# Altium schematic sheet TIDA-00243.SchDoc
size 431 x 279 mm; Date: Not shown in title block; ApprovedBy: Not shown in title block; CheckedBy: Not shown in title block; Author: Not shown in title block; CompanyName: Not shown in title block; DrawnBy: Gordon Varney; Engineer: Not shown in title block; Organization: Not shown in title block; Address1: Not shown in title block; Address2: Not shown in title block; Address3: Not shown in title block; Address4: Not shown in title block; DocumentNumber: 1; Revision: Use project parameter SCH_Rev; SheetNumber: 1; SheetTotal: 1; PageSetup: Record=PageOptions|CenterHorizontal=True|CenterVertical=True|PrintScale=0.64|XCorrection=1.00|YCorrection=1.00|PrintKind=0|BorderSize=5000000|LeftOffset=0|BottomOffset=0|Orientation=2|PaperLength=1000|PaperWidth=1000|Scale=100|PaperSource=15|PrintQuality=600|MediaType=1|DitherType=10|PaperKind=Letter|PrintScaleMode=1
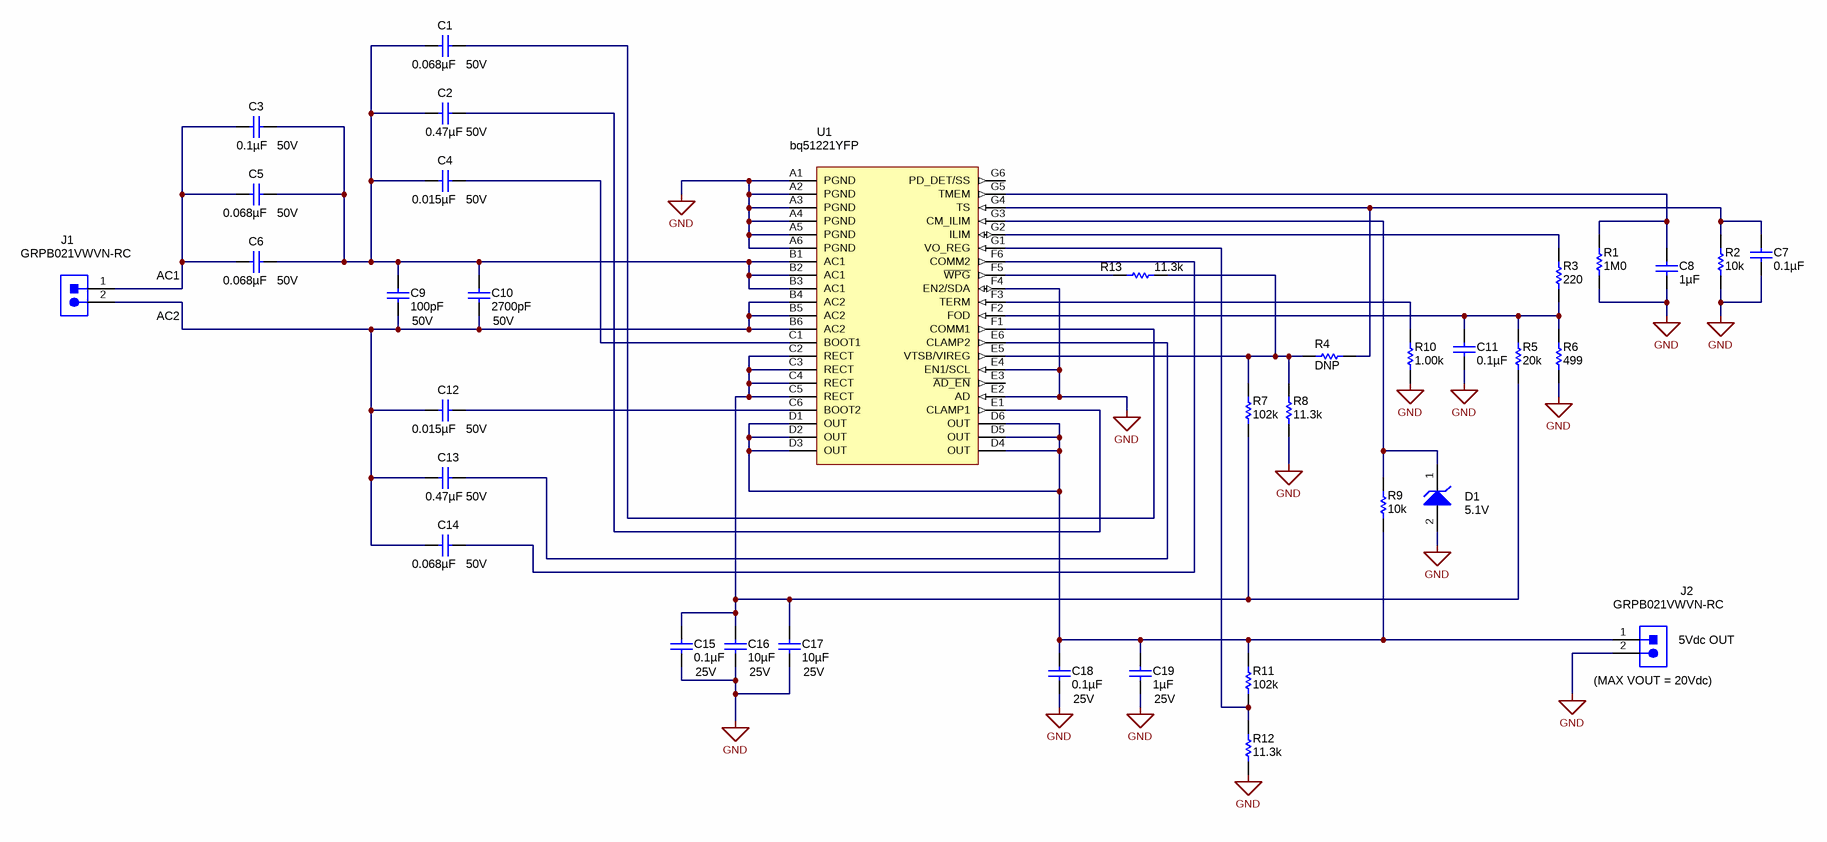
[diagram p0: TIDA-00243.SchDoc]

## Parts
C1  ValueDisplayed: 0.068µF  Value2: 50V  [0402]  (hidden comment: C1005X7R1H683K)
C2  ValueDisplayed: 0.47µF  Value2: 50V  [0402]  (hidden comment: UMK105ABJ474KV-F)
C3  ValueDisplayed: 0.1µF  Value2: 50V  [0402]  (hidden comment: C1005X7R1H104K)
C4  ValueDisplayed: 0.015µF  Value2: 50V  [0402]  (hidden comment: GRM155R71H153KA12D)
C5  ValueDisplayed: 0.068µF  Value2: 50V  [0402]  (hidden comment: C1005X7R1H683K)
C6  ValueDisplayed: 0.068µF  Value2: 50V  [0402]  (hidden comment: C1005X7R1H683K)
C7  ValueDisplayed: 0.1µF  [0201]  (hidden comment: C0603X5R1E104K030BB)
C8  ValueDisplayed: 1µF  [0201]  (hidden comment: CL03A105MP3NSNC)
C9  ValueDisplayed: 100pF  Value2: 50V  [0402]  (hidden comment: GRM1555C1H101JA01D)
C10  ValueDisplayed: 2700pF  Value2: 50V  [0402]  (hidden comment: GRM155R71H272KA01J)
C11  ValueDisplayed: 0.1µF  [0201]  (hidden comment: C0603X5R1E104K030BB)
C12  ValueDisplayed: 0.015µF  Value2: 50V  [0402]  (hidden comment: GRM155R71H153KA12D)
C13  ValueDisplayed: 0.47µF  Value2: 50V  [0402]  (hidden comment: UMK105ABJ474KV-F)
C14  ValueDisplayed: 0.068µF  Value2: 50V  [0402]  (hidden comment: C1005X7R1H683K)
C15  ValueDisplayed: 0.1µF  Value2: 25V  [0201]  (hidden comment: C0603X5R1E104K030BB)
C16  ValueDisplayed: 10µF  Value2: 25V  [0603]  (hidden comment: GRM188R61E106MA73D)
C17  ValueDisplayed: 10µF  Value2: 25V  [0603]  (hidden comment: GRM188R61E106MA73D)
C18  ValueDisplayed: 0.1µF  Value2: 25V  [0201]  (hidden comment: C0603X5R1E104K030BB)
C19  ValueDisplayed: 1µF  Value2: 25V  [0402]  (hidden comment: CGB2A1X5R1E105K033BC)
D1  value 5.1V  [SOD-523]  (hidden comment: BZT52C5V1T-7)
J1  GRPB021VWVN-RC  [Sullins_GRPB021VWVN-RC]
J2  GRPB021VWVN-RC  [Sullins_GRPB021VWVN-RC]
R1  value 1M0  [0201M]  (hidden comment: ERJ-1GEF1004C)
R2  value 10k  [0201M]  (hidden comment: ERJ-1GEF1002C)
R3  value 220  [0201M]  (hidden comment: ERJ-1GEF2200C)
R4  value DNP  [0201M]  (hidden comment: ERJ-1GEF2002C)
R5  value 20k  [0201M]  (hidden comment: ERJ-1GEF2002C)
R6  value 499  [0201M]  (hidden comment: ERJ-1GEF4990C)
R7  value 102k  [0201M]  (hidden comment: ERJ-1GEF1023C)
R8  value 11.3k  [0201M]  (hidden comment: ERJ-1GEF1132C)
R9  value 10k  [0201M]  (hidden comment: ERJ-1GEF1002C)
R10  value 1.00k  [0201M]  (hidden comment: ERJ-1GEF1001C)
R11  value 102k  [0201M]  (hidden comment: ERJ-1GEF1023C)
R12  value 11.3k  [0201M]  (hidden comment: ERJ-1GEF1132C)
R13  value 11.3k  [0201M]  (hidden comment: ERJ-1GEF1132C)
U1  bq5102x  [YFP0042AWCG]  (value not drawn)

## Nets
GND: C7.2 C8.2 C11.2 C15.2 C16.2 C17.2 C18.2 C19.2 D1.2(A) J2.2 R1.1 R2.1 R6.1 R8.1 R10.1 R12.1 U1.A1(PGND) U1.A2(PGND) U1.A3(PGND) U1.A4(PGND) U1.A5(PGND) U1.A6(PGND) U1.E2(AD) U1.E4(EN1/SCL) U1.F4(EN2/SDA)
NetC1_1: C1.1 U1.F1(COMM1)
NetC1_2: C1.2 C2.2 C3.1 C4.2 C5.1 C6.1 C9.1 C10.1 U1.B1(AC1) U1.B2(AC1) U1.B3(AC1)
NetC2_1: C2.1 U1.E1(CLAMP1)
NetC3_2: C3.2 C5.2 C6.2 J1.1
NetC4_1: C4.1 U1.C1(BOOT1)
NetC7_1: C7.1 R2.2 R4.2 U1.G4(TS)
NetC8_1: C8.1 R1.2 U1.G5(TMEM)
NetC9_2: C9.2 C10.2 C12.2 C13.2 C14.2 J1.2 U1.B4(AC2) U1.B5(AC2) U1.B6(AC2)
NetC11_1: C11.1 R3.1 R5.2 R6.2 U1.F2(FOD)
NetC12_1: C12.1 U1.C6(BOOT2)
NetC13_1: C13.1 U1.E6(CLAMP2)
NetC14_1: C14.1 U1.F6(COMM2)
NetC15_1: C15.1 C16.1 C17.1 R5.1 R7.1 U1.C2(RECT) U1.C3(RECT) U1.C4(RECT) U1.C5(RECT)
NetC18_1: C18.1 C19.1 J2.1 R9.1 R11.2 U1.D1(OUT) U1.D2(OUT) U1.D3(OUT) U1.D4(OUT) U1.D5(OUT) U1.D6(OUT)
NetD1_1: D1.1(K) R9.2 U1.G3(CM_ILIM)
NetR3_2: R3.2 U1.G2(ILIM)
NetR4_1: R4.1 R7.2 R8.2 R13.1 U1.E5(VTSB/VIREG)
NetR10_2: R10.2 U1.F3(TERM)
NetR11_1: R11.1 R12.2 U1.G1(VO_REG)
NetR13_2: R13.2 U1.F5(~{WPG})

Not connected (* = marked no-connect by the designer): U1 E3(~{AD_EN}) G6(PD_DET/SS)

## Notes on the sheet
- AC1
- AC2
- (near J2) 5Vdc OUT
- (near J2) (MAX VOUT = 20Vdc)

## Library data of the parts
C1 C5 C6 C14 = C1005X7R1H683K: CAP, CERM, 0.068uF, 50V, +/-10%, C0G/NP0, 0402; Manufacturer: TDK; Polarized: N; CompType: Capacitor; U/M: EA; Cap_F: 0.000000068; Tolerance_%: 10; Value1: Unknown; VDC_V: 50; TaMin_C: -55; TaMax_C: 125
C2 C13 = GRM155R61A474KE15D: CAP, CERM, 0.47uF, 50V, +/-10%, X5R, 0402; Manufacturer: Taiyo Yuden; Polarized: N; CompType: Capacitor; U/M: EA; Cap_F: 0.00000047; Tolerance_%: 10; Value1: Unknown; VDC_V: 50; TaMin_C: -55; TaMax_C: 85
C3 = C1005X7R1H104K: CAP, CERM, 0.1uF, 50V, +/-10%, C0G/NP0, 0402; Manufacturer: TDK; Polarized: N; CompType: Capacitor; U/M: EA; Cap_F: 0.0000001; Tolerance_%: 10; Value1: Unknown; VDC_V: 50; TaMin_C: -55; TaMax_C: 125
C4 C12 = GRM155R71H153KA12D: CAP, CERM, 0.015uF, 50V, +/-10%, X7R, 0402; Manufacturer: MuRata; Polarized: N; CompType: Capacitor; U/M: EA; Cap_F: 0.000000015; Tolerance_%: 10; Value1: Unknown; VDC_V: 50; TaMin_C: -55; TaMax_C: 125
C7 C11 C15 C18 = C0603X5R0J103K: CAP, CERM, 0.1uF, 25V, +/-10%, X5R, 0201; Manufacturer: TDK; Polarized: N; CompType: Capacitor; U/M: EA; Cap_F: 0.00000001; Tolerance_%: 10; Value1: Unknown; VDC_V: 25; TaMin_C: -55; TaMax_C: 85
C8 = CL03A105MP3NSNC: CAP, CERM, 1uF, 10V, +/-20%, X5R, 0201; Manufacturer: Samsung; Polarized: N; CompType: Capacitor; U/M: EA; Cap_F: 0.000001; Tolerance_%: 20; Value1: Unknown; VDC_V: 10; TaMin_C: -55; TaMax_C: 85
C9 = GRM1555C1H101JA01D: CAP, CERM, 100pF, 50V, +/-5%, C0G/NP0, 0402; Manufacturer: MuRata; Polarized: N; CompType: Capacitor; U/M: EA; Cap_F: 0.0000000001; Tolerance_%: 5; Value1: Unknown; VDC_V: 50; TaMin_C: -55; TaMax_C: 125
C10 = GRM155R71H222KA01D: CAP, CERM, 2700pF, 50V, +/-10%, X7R, 0402; Manufacturer: MuRata; Polarized: N; CompType: Capacitor; U/M: EA; Cap_F: 0.0000000022; Tolerance_%: 10; Value1: Unknown; VDC_V: 50; TaMin_C: -55; TaMax_C: 125
C16 C17 = GRM188R61E105KA12D: CAP, CERM, 10uF, 25V, +/-10%, X5R, 0603; Manufacturer: MuRata; Polarized: N; CompType: Capacitor; U/M: EA; Cap_F: 0.000001; Tolerance_%: 10; Value1: Unknown; VDC_V: 25; TaMin_C: -55; TaMax_C: 85
C19 = GRM155R61A105KE15D: CAP, CERM, 1uF, 25V, +/-10%, X5R, 0402; Manufacturer: TDK; Polarized: N; CompType: Capacitor; U/M: EA; Cap_F: 0.000001; Tolerance_%: 10; Value1: Unknown; VDC_V: 25; TaMin_C: -55; TaMax_C: 85
D1 = BZT52C5V1T-7: Diode, Zener, 5.1V, 300mW, SOD-523; Manufacturer: Diodes Inc.; U/M: EA; Power_W: 0.3; Vz_V: 5.1; Value1: 0.3W; RJA_CperW: 417
J1 J2 = GRPB021VWVN-RC: Header male, 2x1, 50mil, TH; Manufacturer: Sullins Connector Solutions; SymbolCreator: a0412235; U/M: EA
R1 = ERJ-1GE0R00C: RES, 1M0 ohm, 1%, 0.05W, 0201; Manufacturer: Panasonic; CompType: Resistor; Res_ohm: 0; Value_Code: 0000; Tolerance_%: 5; Power_W: 0.05; VDC_V: 15; TempCo: 600 ppm/C; EIA_Code: E24; U/M: EA
R2 R9 = ERJ-1GE0R00C: RES, 10k ohm, 1%, 0.05W, 0201; Manufacturer: Panasonic; CompType: Resistor; Res_ohm: 0; Value_Code: 0000; Tolerance_%: 5; Power_W: 0.05; VDC_V: 15; TempCo: 600 ppm/C; EIA_Code: E24; U/M: EA
R3 = ERJ-1GE0R00C: RES, 220 ohm, 1%, 0.05W, 0201; Manufacturer: Panasonic; CompType: Resistor; Res_ohm: 0; Value_Code: 0000; Tolerance_%: 5; Power_W: 0.05; VDC_V: 15; TempCo: 600 ppm/C; EIA_Code: E24; U/M: EA
R4 R5 = ERJ-1GE0R00C: RES, 20k ohm, 1%, 0.05W, 0201; Manufacturer: Panasonic; CompType: Resistor; Res_ohm: 0; Value_Code: 0000; Tolerance_%: 5; Power_W: 0.05; VDC_V: 15; TempCo: 600 ppm/C; EIA_Code: E24; U/M: EA
R6 = CRCW0201499RFKED: RES, 499 ohm, 1%, 0.05W, 0201; Manufacturer: Vishay-Dale; CompType: Resistor; Value_Code: 499R; Tolerance_%: 1; Power_W: 0.05; VDC_V: 30; TempCo: 100 ppm/C; EIA_Code: E96; U/M: EA
R7 R11 = ERJ-1GE0R00C: RES, 102k ohm, 1%, 0.05W, 0201; Manufacturer: Panasonic; CompType: Resistor; Res_ohm: 0; Value_Code: 0000; Tolerance_%: 5; Power_W: 0.05; VDC_V: 15; TempCo: 600 ppm/C; EIA_Code: E24; U/M: EA
R8 R12 R13 = ERJ-1GE0R00C: RES, 11.3k ohm, 1%, 0.05W, 0201; Manufacturer: Panasonic; CompType: Resistor; Res_ohm: 0; Value_Code: 0000; Tolerance_%: 5; Power_W: 0.05; VDC_V: 15; TempCo: 600 ppm/C; EIA_Code: E24; U/M: EA
R10 = ERJ-1GE0R00C: RES, 1.00k ohm, 1%, 0.05W, 0201; Manufacturer: Panasonic; CompType: Resistor; Res_ohm: 0; Value_Code: 0000; Tolerance_%: 5; Power_W: 0.05; VDC_V: 15; TempCo: 600 ppm/C; EIA_Code: E24; U/M: EA
U1 = bq51221YFP: DUAL MODE (Qi and PMA) INTEGRATED WIRELESS RECEIVER POWER SUPPLY, YFP0042AWCG; Alternate Manufacturer: None; Manufacturer: Texas Instruments; SymbolCreator: a0799628; CompType: IC; U/M: EA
